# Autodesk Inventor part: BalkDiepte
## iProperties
Created: 2010-03
Part Number: BalkDiepte
Document SubType Name: Modeling
Designer: Ferry
Density: 1 g/cm^3
Author: Ferry
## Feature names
1. Extrusion1
